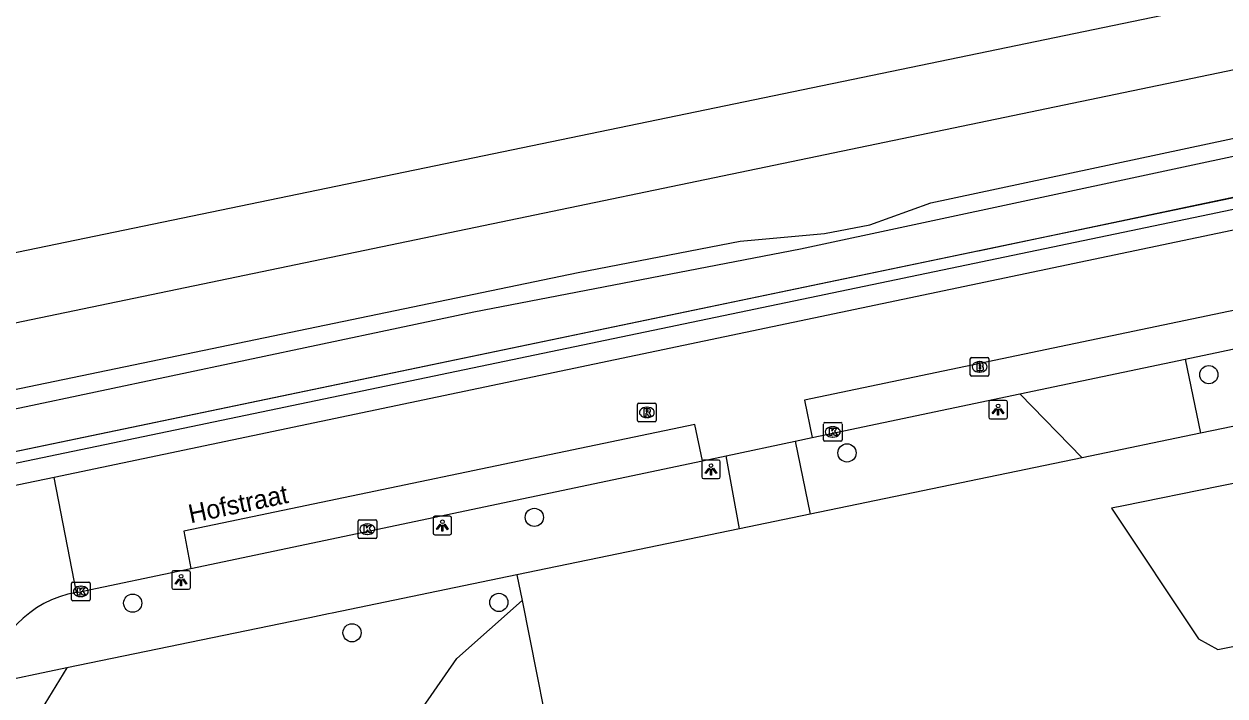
# Model space of a CAD drawing. Extents: x 162990 to 165007, y 383433 to 384336.
# Drawn here: x 163723.1 to 163787.6, y 384090.3 to 384126.4 of the extents above; entities that cross this region are included whole.
import ezdxf

# ---------------------------------------------------------------- set-up
doc = ezdxf.new("R2010")
doc.units = 0
for name, color, linetype in [('IMGEO_Boom', 7, 'Continuous'), ('IMGEO_Brandkraan', 7, 'Continuous'), ('IMGEO_Greppel_droge_sloot', 7, 'Continuous'), ('IMGEO_Groenvoorziening', 7, 'Continuous'), ('IMGEO_Haag', 7, 'Continuous'), ('IMGEO_Hek', 7, 'Continuous'), ('IMGEO_Kolk', 7, 'Continuous'), ('IMGEO_Lichtpunt', 7, 'Continuous'), ('IMGEO_Openbare_ruimte_label', 7, 'Continuous'), ('IMGEO_Pand', 7, 'Continuous'), ('IMGEO_Rijbaan_lokaal_gesloten', 7, 'Continuous'), ('IMGEO_Rijbaan_lokaal_open', 7, 'Continuous'), ('IMGEO_Rioolput', 7, 'Continuous'), ('IMGEO_Spoor', 7, 'Continuous'), ('IMGEO_Spoorbaan_halfverhard', 7, 'Continuous'), ('IMGEO_Voetpad_open', 7, 'Continuous')]:
    doc.layers.add(name, color=color, linetype=linetype)

msp = doc.modelspace()

# ---------------------------------------------------------------- linework, layer by layer
at = {"layer": 'IMGEO_Boom'}
for centre in [(163786.74, 384107.563), (163767.31, 384103.363), (163750.522, 384099.899), (163728.959, 384095.293), (163748.619, 384095.332), (163740.736, 384093.702)]:
    msp.add_circle(centre, 0.489, dxfattribs=at)
at = {"layer": 'IMGEO_Brandkraan'}
for p, q in [((163774.005, 384108.485), (163774.857, 384108.485)), ((163773.93, 384107.559), (163773.93, 384108.411)), ((163774.418, 384108.265), (163774.443, 384108.265)), ((163774.931, 384108.411), (163774.931, 384107.559)), ((163774.857, 384107.485), (163774.005, 384107.485)), ((163774.441, 384107.705), (163774.416, 384107.705))]:
    msp.add_line(p, q, dxfattribs=at)
for points in [[(163774.005, 384108.485), (163774.857, 384108.485)], [(163773.93, 384107.559), (163773.93, 384108.411)], [(163774.278, 384108.185), (163774.278, 384107.785), (163774.491, 384107.785)], [(163774.509, 384108.185), (163774.278, 384108.185)], [(163774.457, 384108.104), (163774.403, 384108.104), (163774.403, 384108.028)], [(163774.403, 384108.028), (163774.456, 384108.028)], [(163774.465, 384107.952), (163774.403, 384107.952), (163774.403, 384107.871)], [(163774.403, 384107.871), (163774.465, 384107.871)], [(163774.931, 384108.411), (163774.931, 384107.559)], [(163774.857, 384107.485), (163774.005, 384107.485)]]:
    msp.add_lwpolyline(points, dxfattribs=at)
for centre, radius, start, end in [((163774.007, 384108.409), 0.0765, 91.55205, 178.44795), ((163774.007, 384108.409), 0.0765, 91.55205, 178.44795), ((163774.855, 384108.409), 0.0765, 1.55205, 88.44795), ((163774.855, 384108.409), 0.0765, 1.55205, 88.44795), ((163774.458, 384108.066), 0.0379, 267.82845, 90.93552), ((163774.466, 384107.911), 0.0404, 269.87594, 90.50774), ((163774.497, 384108.036), 0.251, 268.66757, 293.53466), ((163774.513, 384108.04), 0.145, 59.4692, 91.53667), ((163774.538, 384108.087), 0.0922, 285.51372, 58.15012), ((163774.543, 384107.895), 0.105, 301.31148, 78.98903), ((163774.007, 384107.561), 0.0765, 181.55205, 268.44795), ((163774.007, 384107.561), 0.0765, 181.55205, 268.44795), ((163774.855, 384107.561), 0.0765, 271.55205, 358.44795), ((163774.855, 384107.561), 0.0765, 271.55205, 358.44795)]:
    msp.add_arc(centre, radius, start, end, dxfattribs=at)
for centre, major_axis, ratio, start_param, end_param in [((163774.417, 384107.985), (-0.387, 0.002), 0.722429, 4.712389, 7.853982), ((163774.442, 384107.985), (-0.39, 0.002), 0.717154, 1.570796, 4.712389)]:
    msp.add_ellipse(centre, major_axis=major_axis, ratio=ratio, start_param=start_param, end_param=end_param, dxfattribs=at)
at = {"layer": 'IMGEO_Greppel_droge_sloot'}
for points in [[(163576.539, 384075.585), (163580.225, 384075.843), (163582.595, 384076.149), (163591.319, 384078.544), (163611.48, 384082.911), (163632.818, 384087.115), (163635.979, 384087.485), (163644.815, 384089.481), (163662.394, 384093.293), (163672.09, 384095.145), (163681.423, 384097.117), (163695.738, 384099.89), (163713.242, 384103.924), (163722.892, 384105.78), (163747.271, 384110.947), (163764.809, 384114.316), (163834.463, 384129.25), (163837.931, 384129.88), (163838.592, 384129.42), (163838.715, 384128.865), (163838.4, 384128.258), (163837.828, 384127.908), (163837.073, 384127.674), (163829.276, 384125.722)], [(163829.276, 384125.722), (163820.911, 384123.918), (163796.575, 384118.842), (163721.236, 384103.128), (163651.615, 384088.607), (163609.784, 384079.965), (163577.034, 384073.199)]]:
    msp.add_lwpolyline(points, dxfattribs=at)
at = {"layer": 'IMGEO_Groenvoorziening'}
for points in [[(163749.589, 384096.809), (163749.862, 384095.435)], [(163744.543, 384089.683), (163746.357, 384092.316), (163749.862, 384095.435)], [(163749.862, 384095.435), (163753.778, 384075.735), (163753.801, 384075.617)]]:
    msp.add_lwpolyline(points, dxfattribs=at)
at = {"layer": 'IMGEO_Haag'}
msp.add_lwpolyline([(163408.734, 384037.023), (163409.522, 384037.258), (163419.713, 384040.294), (163422.158, 384040.849), (163459.771, 384048.486), (163651.736, 384088.019), (163830.895, 384125.387)], dxfattribs=at)
at = {"layer": 'IMGEO_Hek'}
for points in [[(163774.371, 384114.211), (163806.617, 384121.018), (163830.855, 384126.062), (163844.511, 384128.802), (163854.414, 384130.95), (163855.366, 384133.259)], [(163830.751, 384125.97), (163651.615, 384088.607), (163494.89, 384056.228), (163459.651, 384049.074)]]:
    msp.add_lwpolyline(points, dxfattribs=at)
at = {"layer": 'IMGEO_Kolk'}
for p, q in [((163766.048, 384104.064), (163766.048, 384104.916)), ((163766.123, 384104.99), (163766.975, 384104.99)), ((163766.536, 384104.77), (163766.561, 384104.77)), ((163767.049, 384104.916), (163767.049, 384104.064)), ((163766.975, 384103.99), (163766.123, 384103.99)), ((163766.559, 384104.21), (163766.534, 384104.21)), ((163741.061, 384098.839), (163741.061, 384099.691)), ((163741.136, 384099.765), (163741.988, 384099.765)), ((163741.549, 384099.545), (163741.574, 384099.545)), ((163742.062, 384099.691), (163742.062, 384098.839)), ((163741.988, 384098.765), (163741.136, 384098.765)), ((163741.572, 384098.985), (163741.547, 384098.985)), ((163725.671, 384095.497), (163725.671, 384096.349)), ((163725.746, 384096.423), (163726.598, 384096.423)), ((163726.159, 384096.203), (163726.184, 384096.203)), ((163726.672, 384096.349), (163726.672, 384095.497)), ((163726.182, 384095.643), (163726.157, 384095.643)), ((163726.598, 384095.423), (163725.746, 384095.423))]:
    msp.add_line(p, q, dxfattribs=at)
for points in [[(163766.048, 384104.064), (163766.048, 384104.916)], [(163766.123, 384104.99), (163766.975, 384104.99)], [(163766.369, 384104.69), (163766.492, 384104.69), (163766.492, 384104.539), (163766.622, 384104.69), (163766.786, 384104.69), (163766.64, 384104.539), (163766.793, 384104.29), (163766.641, 384104.29), (163766.556, 384104.454), (163766.492, 384104.387), (163766.492, 384104.29), (163766.369, 384104.29), (163766.369, 384104.69)], [(163767.049, 384104.916), (163767.049, 384104.064)], [(163766.975, 384103.99), (163766.123, 384103.99)], [(163741.061, 384098.839), (163741.061, 384099.691)], [(163741.136, 384099.765), (163741.988, 384099.765)], [(163741.382, 384099.465), (163741.505, 384099.465), (163741.505, 384099.314), (163741.635, 384099.465), (163741.799, 384099.465), (163741.653, 384099.314), (163741.806, 384099.065), (163741.654, 384099.065), (163741.569, 384099.229), (163741.505, 384099.162), (163741.505, 384099.065), (163741.382, 384099.065), (163741.382, 384099.465)], [(163742.062, 384099.691), (163742.062, 384098.839)], [(163741.988, 384098.765), (163741.136, 384098.765)], [(163725.671, 384095.497), (163725.671, 384096.349)], [(163725.746, 384096.423), (163726.598, 384096.423)], [(163726.672, 384096.349), (163726.672, 384095.497)], [(163725.992, 384096.123), (163726.115, 384096.123), (163726.115, 384095.972), (163726.245, 384096.123), (163726.409, 384096.123), (163726.263, 384095.972), (163726.416, 384095.723), (163726.264, 384095.723), (163726.179, 384095.887), (163726.115, 384095.82), (163726.115, 384095.723), (163725.992, 384095.723), (163725.992, 384096.123)], [(163726.598, 384095.423), (163725.746, 384095.423)]]:
    msp.add_lwpolyline(points, dxfattribs=at)
for centre, start, end in [((163766.125, 384104.914), 91.55205, 178.44795), ((163766.125, 384104.914), 91.55205, 178.44795), ((163766.973, 384104.914), 1.55205, 88.44795), ((163766.973, 384104.914), 1.55205, 88.44795), ((163766.125, 384104.066), 181.55205, 268.44795), ((163766.125, 384104.066), 181.55205, 268.44795), ((163766.973, 384104.066), 271.55205, 358.44795), ((163766.973, 384104.066), 271.55205, 358.44795), ((163741.138, 384099.689), 91.55205, 178.44795), ((163741.138, 384099.689), 91.55205, 178.44795), ((163741.986, 384099.689), 1.55205, 88.44795), ((163741.986, 384099.689), 1.55205, 88.44795), ((163741.138, 384098.841), 181.55205, 268.44795), ((163741.138, 384098.841), 181.55205, 268.44795), ((163741.986, 384098.841), 271.55205, 358.44795), ((163741.986, 384098.841), 271.55205, 358.44795), ((163725.748, 384096.347), 91.55205, 178.44795), ((163725.748, 384096.347), 91.55205, 178.44795), ((163726.596, 384096.347), 1.55205, 88.44795), ((163726.596, 384096.347), 1.55205, 88.44795), ((163725.748, 384095.499), 181.55205, 268.44795), ((163725.748, 384095.499), 181.55205, 268.44795), ((163726.596, 384095.499), 271.55205, 358.44795), ((163726.596, 384095.499), 271.55205, 358.44795)]:
    msp.add_arc(centre, 0.0765, start, end, dxfattribs=at)
for centre, major_axis, ratio, start_param, end_param in [((163766.535, 384104.49), (-0.387, 0.002), 0.722429, 4.712389, 7.853982), ((163766.56, 384104.49), (-0.39, 0.002), 0.717154, 1.570796, 4.712389), ((163741.548, 384099.265), (-0.387, 0.002), 0.722429, 4.712389, 7.853982), ((163741.573, 384099.265), (-0.39, 0.002), 0.717154, 1.570796, 4.712389), ((163726.158, 384095.923), (-0.387, 0.002), 0.722429, 4.712389, 7.853982), ((163726.183, 384095.923), (-0.39, 0.002), 0.717154, 1.570796, 4.712389)]:
    msp.add_ellipse(centre, major_axis=major_axis, ratio=ratio, start_param=start_param, end_param=end_param, dxfattribs=at)
at = {"layer": 'IMGEO_Lichtpunt'}
for p, q in [((163774.925, 384106.092), (163774.925, 384105.285)), ((163774.925, 384106.092), (163774.925, 384105.285)), ((163775.827, 384106.187), (163775.019, 384106.187)), ((163775.827, 384106.187), (163775.019, 384106.187)), ((163775.921, 384105.285), (163775.921, 384106.092)), ((163775.921, 384105.285), (163775.921, 384106.092)), ((163775.019, 384105.191), (163775.827, 384105.191)), ((163775.019, 384105.191), (163775.827, 384105.191)), ((163759.511, 384102.882), (163759.511, 384102.075)), ((163759.511, 384102.882), (163759.511, 384102.075)), ((163760.413, 384102.977), (163759.605, 384102.977)), ((163760.413, 384102.977), (163759.605, 384102.977)), ((163760.507, 384102.075), (163760.507, 384102.882)), ((163760.507, 384102.075), (163760.507, 384102.882)), ((163759.605, 384101.981), (163760.413, 384101.981)), ((163759.605, 384101.981), (163760.413, 384101.981)), ((163745.086, 384099.867), (163745.086, 384099.06)), ((163745.086, 384099.867), (163745.086, 384099.06)), ((163745.988, 384099.962), (163745.18, 384099.962)), ((163745.988, 384099.962), (163745.18, 384099.962)), ((163746.082, 384099.06), (163746.082, 384099.867)), ((163746.082, 384099.06), (163746.082, 384099.867)), ((163745.18, 384098.966), (163745.988, 384098.966)), ((163745.18, 384098.966), (163745.988, 384098.966)), ((163731.056, 384096.937), (163731.056, 384096.13)), ((163731.056, 384096.937), (163731.056, 384096.13)), ((163731.958, 384097.032), (163731.15, 384097.032)), ((163731.958, 384097.032), (163731.15, 384097.032)), ((163732.052, 384096.13), (163732.052, 384096.937)), ((163732.052, 384096.13), (163732.052, 384096.937)), ((163731.15, 384096.036), (163731.958, 384096.036)), ((163731.15, 384096.036), (163731.958, 384096.036))]:
    msp.add_line(p, q, dxfattribs=at)
for points in [[(163775.299, 384105.756), (163775.338, 384105.728), (163775.15, 384105.466), (163775.112, 384105.493), (163775.299, 384105.756)], [(163775.401, 384105.708), (163775.448, 384105.708), (163775.448, 384105.386), (163775.401, 384105.386), (163775.401, 384105.708)], [(163775.511, 384105.728), (163775.549, 384105.755), (163775.736, 384105.493), (163775.697, 384105.465), (163775.511, 384105.728)], [(163759.885, 384102.546), (163759.924, 384102.518), (163759.736, 384102.256), (163759.698, 384102.283), (163759.885, 384102.546)], [(163759.987, 384102.498), (163760.034, 384102.498), (163760.034, 384102.176), (163759.987, 384102.176), (163759.987, 384102.498)], [(163760.097, 384102.518), (163760.135, 384102.545), (163760.322, 384102.283), (163760.283, 384102.255), (163760.097, 384102.518)], [(163745.46, 384099.531), (163745.499, 384099.503), (163745.311, 384099.241), (163745.273, 384099.268), (163745.46, 384099.531)], [(163745.562, 384099.483), (163745.609, 384099.483), (163745.609, 384099.161), (163745.562, 384099.161), (163745.562, 384099.483)], [(163745.672, 384099.503), (163745.71, 384099.53), (163745.897, 384099.268), (163745.858, 384099.24), (163745.672, 384099.503)], [(163731.43, 384096.601), (163731.469, 384096.573), (163731.281, 384096.311), (163731.243, 384096.338), (163731.43, 384096.601)], [(163731.532, 384096.553), (163731.579, 384096.553), (163731.579, 384096.231), (163731.532, 384096.231), (163731.532, 384096.553)], [(163731.642, 384096.573), (163731.68, 384096.6), (163731.867, 384096.338), (163731.828, 384096.31), (163731.642, 384096.573)]]:
    msp.add_lwpolyline(points, dxfattribs=at)
for centre in [(163775.424, 384105.89), (163760.01, 384102.68), (163745.585, 384099.665), (163731.555, 384096.735)]:
    msp.add_circle(centre, 0.0994, dxfattribs=at)
for centre, start, end in [((163775.019, 384106.092), 90, 180), ((163775.019, 384106.092), 90, 180), ((163775.827, 384106.092), 0, 90), ((163775.827, 384106.092), 0, 90), ((163775.019, 384105.285), 180, 270), ((163775.019, 384105.285), 180, 270), ((163775.827, 384105.285), 270, 0), ((163775.827, 384105.285), 270, 360), ((163759.605, 384102.882), 90, 180), ((163759.605, 384102.882), 90, 180), ((163760.413, 384102.882), 0, 90), ((163760.413, 384102.882), 0, 90), ((163759.605, 384102.075), 180, 270), ((163759.605, 384102.075), 180, 270), ((163760.413, 384102.075), 270, 0), ((163760.413, 384102.075), 270, 360), ((163745.18, 384099.867), 90, 180), ((163745.18, 384099.867), 90, 180), ((163745.988, 384099.867), 0, 90), ((163745.988, 384099.867), 0, 90), ((163745.18, 384099.06), 180, 270), ((163745.18, 384099.06), 180, 270), ((163745.988, 384099.06), 270, 0), ((163745.988, 384099.06), 270, 360), ((163731.15, 384096.937), 90, 180), ((163731.15, 384096.937), 90, 180), ((163731.958, 384096.937), 0, 90), ((163731.958, 384096.937), 0, 90), ((163731.15, 384096.13), 180, 270), ((163731.15, 384096.13), 180, 270), ((163731.958, 384096.13), 270, 0), ((163731.958, 384096.13), 270, 360)]:
    msp.add_arc(centre, 0.0946, start, end, dxfattribs=at)
at = {"layer": 'IMGEO_Pand'}
msp.add_lwpolyline([(163796.06, 384103.375), (163793.132, 384102.737), (163787.257, 384101.551), (163782.154, 384100.521), (163781.507, 384100.39), (163786.191, 384093.378), (163787.216, 384092.796), (163788.117, 384092.979), (163788.952, 384093.148), (163791.594, 384093.683), (163792.173, 384090.826), (163795.562, 384091.51), (163797.234, 384091.847), (163797.879, 384088.652), (163799.395, 384088.958), (163799.143, 384090.209), (163800.986, 384090.689), (163802.878, 384091.994)], dxfattribs=at)
at = {"layer": 'IMGEO_Rijbaan_lokaal_gesloten'}
for points in [[(163831.109, 384124.518), (163812.556, 384120.462), (163724.745, 384102.036)], [(163824.909, 384116.702), (163824.503, 384118.628), (163797.649, 384113.01), (163765.036, 384106.198), (163765.448, 384104.188)], [(163759.551, 384102.946), (163759.14, 384104.898), (163731.698, 384099.159), (163732.071, 384097.163)], [(163760.82, 384103.213), (163764.526, 384103.994)], [(163764.526, 384103.994), (163765.448, 384104.188)], [(163759.551, 384102.946), (163760.82, 384103.213)], [(163725.942, 384095.873), (163732.071, 384097.163)]]:
    msp.add_lwpolyline(points, dxfattribs=at)
at = {"layer": 'IMGEO_Rijbaan_lokaal_open'}
for points in [[(163724.745, 384102.036), (163707.965, 384098.574)], [(163725.942, 384095.873), (163724.745, 384102.036)]]:
    msp.add_lwpolyline(points, dxfattribs=at)
msp.add_arc((163726.946, 384090.123), 5.837, 99.90719, 172.04964, dxfattribs=at)
at = {"layer": 'IMGEO_Rioolput'}
for p, q in [((163756.064, 384105.112), (163756.064, 384105.964)), ((163756.139, 384106.038), (163756.991, 384106.038)), ((163757.065, 384105.964), (163757.065, 384105.112)), ((163756.575, 384105.258), (163756.55, 384105.258)), ((163756.552, 384105.818), (163756.577, 384105.818)), ((163756.991, 384105.038), (163756.139, 384105.038))]:
    msp.add_line(p, q, dxfattribs=at)
for points in [[(163756.064, 384105.112), (163756.064, 384105.964)], [(163756.139, 384106.038), (163756.991, 384106.038)], [(163757.065, 384105.964), (163757.065, 384105.112)], [(163756.653, 384105.736), (163756.401, 384105.738), (163756.401, 384105.338)], [(163756.401, 384105.338), (163756.525, 384105.338), (163756.525, 384105.5), (163756.536, 384105.5)], [(163756.579, 384105.657), (163756.525, 384105.657), (163756.525, 384105.576)], [(163756.525, 384105.576), (163756.577, 384105.576)], [(163756.583, 384105.471), (163756.654, 384105.338), (163756.794, 384105.338), (163756.729, 384105.464)], [(163756.991, 384105.038), (163756.139, 384105.038)]]:
    msp.add_lwpolyline(points, dxfattribs=at)
for centre, radius, start, end in [((163756.141, 384105.962), 0.0765, 91.55205, 178.44795), ((163756.141, 384105.962), 0.0765, 91.55205, 178.44795), ((163756.989, 384105.962), 0.0765, 1.55205, 88.44795), ((163756.989, 384105.962), 0.0765, 1.55205, 88.44795), ((163756.535, 384105.447), 0.0533, 26.02933, 88.69889), ((163756.561, 384105.765), 0.19, 274.7715, 282.96867), ((163756.585, 384105.561), 0.0964, 77.00612, 93.18647), ((163756.599, 384105.618), 0.0378, 276.66336, 79.67722), ((163756.652, 384105.626), 0.109, 350.36119, 89.41601), ((163756.65, 384105.626), 0.112, 277.58423, 350.98172), ((163756.634, 384105.411), 0.108, 29.51342, 73.79051), ((163756.141, 384105.114), 0.0765, 181.55205, 268.44795), ((163756.141, 384105.114), 0.0765, 181.55205, 268.44795), ((163756.989, 384105.114), 0.0765, 271.55205, 358.44795), ((163756.989, 384105.114), 0.0765, 271.55205, 358.44795)]:
    msp.add_arc(centre, radius, start, end, dxfattribs=at)
for centre, major_axis, ratio, start_param, end_param in [((163756.551, 384105.538), (-0.387, 0.002), 0.722429, 4.712389, 7.853982), ((163756.576, 384105.538), (-0.39, 0.002), 0.717154, 1.570796, 4.712389)]:
    msp.add_ellipse(centre, major_axis=major_axis, ratio=ratio, start_param=start_param, end_param=end_param, dxfattribs=at)
at = {"layer": 'IMGEO_Spoor'}
for points in [[(164788.231, 384335.773), (164684.182, 384314.23), (164649.743, 384306.978), (164549.034, 384286.117), (164446.504, 384264.637), (164353.435, 384245.24), (164284.243, 384230.902), (164214.646, 384216.358), (164173.585, 384207.909), (164102.605, 384193.066), (164031.754, 384178.409), (163810.752, 384132.353), (163673.071, 384103.86), (163574.904, 384083.455)], [(164789.572, 384332.389), (164775.58, 384329.429), (164644.744, 384302.256), (164570.629, 384286.722), (164345.336, 384239.894), (164220.116, 384213.747), (164092.662, 384187.275), (164071.527, 384182.957), (163942.979, 384156.119), (163900.983, 384147.477), (163806.025, 384127.659), (163575.669, 384079.775)]]:
    msp.add_lwpolyline(points, dxfattribs=at)
at = {"layer": 'IMGEO_Spoorbaan_halfverhard'}
msp.add_lwpolyline([(163721.491, 384106.542), (163752.881, 384113.052), (163761.577, 384114.728), (163766.099, 384115.146), (163768.532, 384115.613), (163771.815, 384116.794), (163789.104, 384120.481), (163810.596, 384124.813), (163831.06, 384129.095), (163835.571, 384129.666), (163837.545, 384130.063), (163841.678, 384131.393), (163843.338, 384131.675)], dxfattribs=at)
at = {"layer": 'IMGEO_Voetpad_open'}
for points in [[(163785.469, 384108.401), (163794.883, 384110.382)], [(163776.585, 384106.531), (163785.469, 384108.401)], [(163785.469, 384108.401), (163786.299, 384104.419)], [(163765.448, 384104.188), (163776.585, 384106.531)], [(163779.935, 384103.1), (163776.585, 384106.531)], [(163796.27, 384106.482), (163795.055, 384106.225), (163786.299, 384104.419)], [(163764.526, 384103.994), (163765.327, 384100.074)], [(163786.299, 384104.419), (163779.935, 384103.1)], [(163732.071, 384097.163), (163759.551, 384102.946)], [(163761.535, 384099.294), (163760.82, 384103.213)], [(163779.935, 384103.1), (163765.327, 384100.074)], [(163765.327, 384100.074), (163761.535, 384099.294)], [(163761.535, 384099.294), (163749.589, 384096.809)], [(163749.589, 384096.809), (163739.659, 384094.755), (163739.473, 384094.717), (163738.472, 384094.511), (163737.505, 384094.313), (163725.422, 384091.811)], [(163725.422, 384091.811), (163721.165, 384090.93)], [(163725.422, 384091.811), (163723.842, 384089.232), (163724.381, 384086.593)]]:
    msp.add_lwpolyline(points, dxfattribs=at)

# ---------------------------------------------------------------- texts
at = {"layer": 'IMGEO_Openbare_ruimte_label'}
msp.add_text('Hofstraat', height=1, rotation=11.8267, dxfattribs=at).set_placement((163732.064, 384099.579))

doc.saveas('drawing.dxf')
